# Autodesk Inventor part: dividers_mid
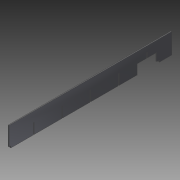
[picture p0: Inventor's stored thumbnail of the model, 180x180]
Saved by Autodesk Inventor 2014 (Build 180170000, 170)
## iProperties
Created: 2014-05
Part Number: dividers_mid
Material: ABS Plastic
Document SubType Name: Modeling
Designer: t_emanb
Density: 1 g/cm^3
Appearance: Smooth - White
Author: t_emanb
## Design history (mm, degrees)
sketch "Sketch1"
  geometry: L1 (0, 0)-(73.101, 0); L2 (73.101, 0)-(73.101, -584.2); L3 (73.101, -584.2)-(0, -584.2); L4 (0, -584.2)-(0, 0); 1 further point
  constraints: 8 end point, 2 parallel, 1 coincident, 1 horizontal, 1 perpendicular
  dimensions: "d0" = 584.2 distance of L1.end L2.end; "d1" = 73.1012 distance of L1.start L1.end
extrude "Extrusion1" new body sketch "Sketch1" distance "d2" = 3.048; taper "d3" = 0 deg
sketch "Sketch2" dims "d9" = 25.4, "d18" = 25.4
  geometry: L1 (0, 0)-(584.2, 0) reference; L2 (584.2, 73.101)-(0, 73.101) reference; L3 (88.9, 73.101)-(88.9, 0); L4 (190.5, 73.101)-(190.5, 0); L5 (292.1, 73.101)-(292.1, 0); L6 (393.7, 73.101)-(393.7, 0); L7 (495.3, 73.101)-(495.3, 0); L8 (87.376, 0)-(90.424, 0); L9 (90.424, 0)-(90.424, 38.1); L10 (90.424, 38.1)-(87.376, 38.1); L11 (87.376, 38.1)-(87.376, 0); L12 (188.976, 38.1)-(188.976, 0); L13 (192.024, 38.1)-(188.976, 38.1); L14 (192.024, 0)-(192.024, 38.1); L15 (188.976, 0)-(192.024, 0); L16 (290.576, 38.1)-(290.576, 0); L17 (293.624, 38.1)-(290.576, 38.1); L18 (293.624, 0)-(293.624, 38.1); L19 (290.576, 0)-(293.624, 0); L20 (392.176, 38.1)-(392.176, 0); L21 (395.224, 38.1)-(392.176, 38.1); L22 (395.224, 0)-(395.224, 38.1); L23 (392.176, 0)-(395.224, 0); L24 (493.776, 38.1)-(493.776, 0); L25 (496.824, 38.1)-(493.776, 38.1); L26 (496.824, 0)-(496.824, 38.1); L27 (493.776, 0)-(496.824, 0); L28 (584.2, 0)-(584.2, 73.101) reference; L29 (493.776, 38.1)-(493.776, 52.781); L30 (493.776, 52.781)-(496.824, 52.781); L31 (496.824, 52.781)-(496.824, 38.1)
  constraints: 56 end point, 3 horizontal, 3 parallel, 3 perpendicular, 3 point on line, 1 collinear, 1 midpoint, 45 other
  dimensions: "d6" = 101.6 distance of L3.start L4.start; "d11" = 3.048 distance of L9.end L10.end; "d12" = 38.1 distance of L10.end L8.start; "d15" = 101.6 distance of L10.end L12.start; "d36" = 20.32 distance between parallel lines of L2 L30
extrude "Extrusion2" cut sketch "Sketch2" stored distance "d20" = 3.175; taper "d21" = 0 deg
sketch "Sketch3"
  geometry: L1 (496.824, 0)-(584.2, 0) reference; L2 (584.2, 0)-(584.2, 73.101) reference; L3 (0, 73.101)-(0, 0) reference; L4 (0, 0)-(87.376, 0) reference; L5 (392.176, 0)-(392.176, 38.1) reference; L6 (0, 6.35)-(6.35, 6.35); L7 (6.35, 6.35)-(6.35, 0)
  constraints: 4 end point, 2 perpendicular, 2 point on line
  dimensions: "d26" = 6.35 distance of L6.end L7.end; "d27" = 6.35 distance of L6.start L6.end
extrude "Extrusion3" cut sketch "Sketch3" stored distance "d24" = 25.4; taper "d25" = 0 deg
sketch "Sketch4"
  geometry: L1 (6.35, 0)-(87.376, 0) reference; L2 (87.376, 38.1)-(90.424, 38.1) reference; L3 (53.975, 0)-(123.825, 0); L4 (123.825, 0)-(123.825, 34.925); L5 (123.825, 34.925)-(53.975, 34.925); L6 (53.975, 34.925)-(53.975, 0); L7 (88.9, 38.1)-(88.9, 0); L8 (293.624, 38.1)-(293.624, 0) reference; L9 (584.2, 73.101)-(0, 73.101) reference; L10 (292.1, 73.101)-(292.1, 0); L11 (460.375, 34.925)-(530.225, 34.925); L12 (530.225, 34.925)-(530.225, 0); L13 (530.225, 0)-(460.375, 0); L14 (460.375, 0)-(460.375, 34.925); 1 further point
  constraints: 20 end point, 4 parallel, 4 symmetric about line, 3 midpoint, 1 horizontal, 1 perpendicular, 1 point on line, 1 other
  dimensions: "d28" = 69.85 distance between parallel lines of L6 L4; "d29" = 34.925 distance of L5.end L3.start
extrude "Extrusion4" cut sketch "Sketch4" stored distance "d30" = 25.4; taper "d31" = 0 deg
sketch "Sketch5"
  geometry: L1 (530.225, 34.925)-(530.225, 0) reference; L2 (530.225, 0)-(584.2, 0) reference; L3 (530.225, 6.35)-(539.75, 6.35); L4 (539.75, 6.35)-(539.75, 0); 4 further points; 1 other entity
  constraints: 4 end point, 2 point on line, 1 horizontal, 1 perpendicular, 1 other
  dimensions: "d32" = 6.35 distance of L3.end L4.end; "d33" = 9.525 distance of L3.start L3.end
extrude "Extrusion5" cut sketch "Sketch5" stored distance "d34" = 25.4; taper "d35" = 0 deg
body "Solid1"
